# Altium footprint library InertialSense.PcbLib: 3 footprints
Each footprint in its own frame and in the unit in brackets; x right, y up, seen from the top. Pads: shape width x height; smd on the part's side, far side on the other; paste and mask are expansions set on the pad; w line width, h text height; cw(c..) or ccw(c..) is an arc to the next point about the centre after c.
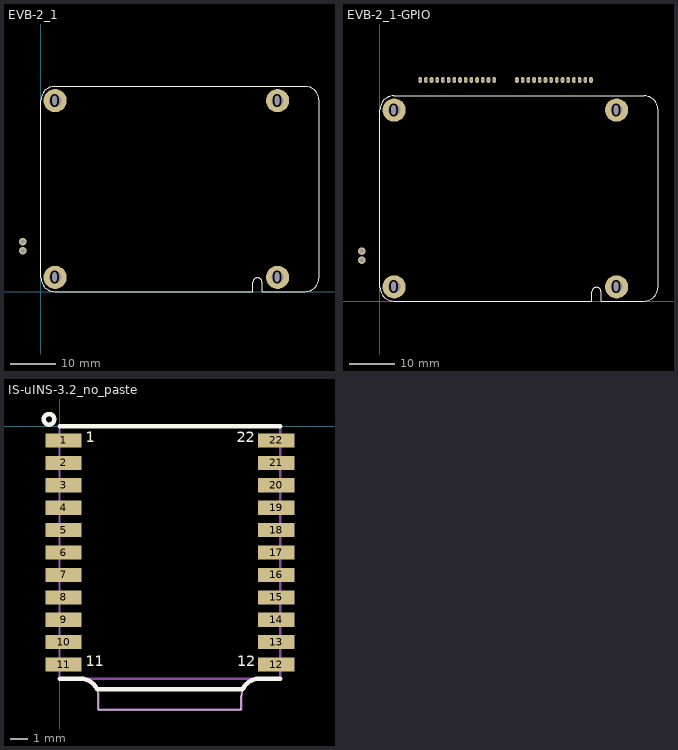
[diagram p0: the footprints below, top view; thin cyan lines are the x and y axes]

## EVB-2_1 [mm] "EVB 2 Footprint"
pads (6):
  round 5.1 hole 2.72: 0(3.1,3.1) 0(3.1,41.9) 0(51.9,3.1) 0(51.9,41.9)
  round 1.65 hole 0.9: H1-1(-4,10.95) H1-2(-4,8.95)
Top Overlay:
  lines w0.1: 0,3 ccw(c3,3) 3,0 46.5,0 46.5,2 cw(c47.5,2) 47.5,3 cw(c47.5,2) 48.5,2 48.5,0 58,0 ccw(c58,3) 61,3 61,42 ccw(c58,42) 58,45 3,45 ccw(c3,42) 0,42 0,3
3D body "EVB-2.step": height 12.61, standoff -0.02, extent -27.055,0 70.775,45

## EVB-2_1-GPIO [mm] "EVB 2.0 Footprint with GPIO headers"
pads (36):
  round 5.1 hole 2.72: 0(3.1,3.1) 0(3.1,41.9) 0(51.9,3.1) 0(51.9,41.9)
  round 1.65 hole 0.9: H1-1(-4,10.95) H1-2(-4,8.95)
  oval 0.8x1.3 / inner round 0.8 / far side oval 0.8x1.3 hole 0.5 paste-2: H7-1(30.05,48.5) H7-1(30.05,48.5) H7-2(31.3,48.5) H7-3(32.55,48.5) H7-4(33.8,48.5) H7-5(35.05,48.5) H7-6(36.3,48.5) H7-7(37.55,48.5) H7-8(38.8,48.5) H7-9(40.05,48.5) H7-10(41.3,48.5) H7-11(42.55,48.5) H7-12(43.8,48.5) H7-13(45.05,48.5) H7-14(46.3,48.5) H8-1(8.8,48.5) H8-1(8.8,48.5) H8-2(10.05,48.5) H8-3(11.3,48.5) H8-4(12.55,48.5) H8-5(13.8,48.5) H8-6(15.05,48.5) H8-7(16.3,48.5) H8-8(17.55,48.5) H8-9(18.8,48.5) H8-10(20.05,48.5) H8-11(21.3,48.5) H8-12(22.55,48.5) H8-13(23.8,48.5) H8-14(25.05,48.5)
Top Overlay:
  lines w0.1: 0,3 ccw(c3,3) 3,0 46.5,0 46.5,2 cw(c47.5,2) 47.5,3 cw(c47.5,2) 48.5,2 48.5,0 58,0 ccw(c58,3) 61,3 61,42 ccw(c58,42) 58,45 3,45 ccw(c3,42) 0,42 0,3
3D body "EVB-2.step": height 12.61, standoff -0.02, extent -27.055,0 70.775,45

## IS-uINS-3.2_no_paste [mm] "Inerial Sense uINS r3.2, 22pins 1.27mm pitch"
height 6.5
pads (22):
  rect 2.05x0.8 smd paste-2.54: 1(0.225,-0.8) 2(0.225,-2.07) 3(0.225,-3.34) 4(0.225,-4.61) 5(0.225,-5.88) 6(0.225,-7.15) 7(0.225,-8.42) 8(0.225,-9.69) 9(0.225,-10.96) 10(0.225,-12.23) 11(0.225,-13.5) 12(12.275,-13.5) 13(12.275,-12.23) 14(12.275,-10.96) 15(12.275,-9.69) 16(12.275,-8.42) 17(12.275,-7.15) 18(12.275,-5.88) 19(12.275,-4.61) 20(12.275,-3.34) 21(12.275,-2.07) 22(12.275,-0.8)
Top Overlay:
  circle w0.254: c-0.6,0.4 r0.3
  lines w0.025: 1.2,-14.3 cw(c1.2,-15.3) 2.2,-15.3 2.2,-16.05 10.3,-16.05 10.3,-15.3 cw(c11.3,-15.3) 11.3,-14.3
  lines w0.254: 0,-14.3 1.3,-14.3 ; 0,0 12.5,0 ; 1.2,-14.3 cw(c1.2,-15.3) 2.106,-14.877 ; 2.2,-14.9 10.3,-14.9 ; 10.394,-14.877 cw(c11.3,-15.3) 11.3,-14.3 ; 11.2,-14.305 12.5,-14.305
  text "22" at 10.048,-1.1 h1.02
  text "12" at 10.075,-13.8 h1.02
  text "11" at 1.473,-13.8 h1.02
  text "1" at 1.473,-1.1 h1.02
Mechanical 13:
  lines w0.127: 0,-14.3 1.2,-14.3 cw(c1.2,-15.3) 2.2,-15.3 2.2,-16.05 10.3,-16.05 10.3,-15.3 cw(c11.3,-15.3) 11.3,-14.3 12.5,-14.3 ; 0,-14.3 0,0 12.5,0 12.5,-14.3 ; 0,-14.3 12.5,-14.3
3D body "uINS-3p2-G2.step": height 4.61, standoff 0.01, extent 0,-15.954 12.5,0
